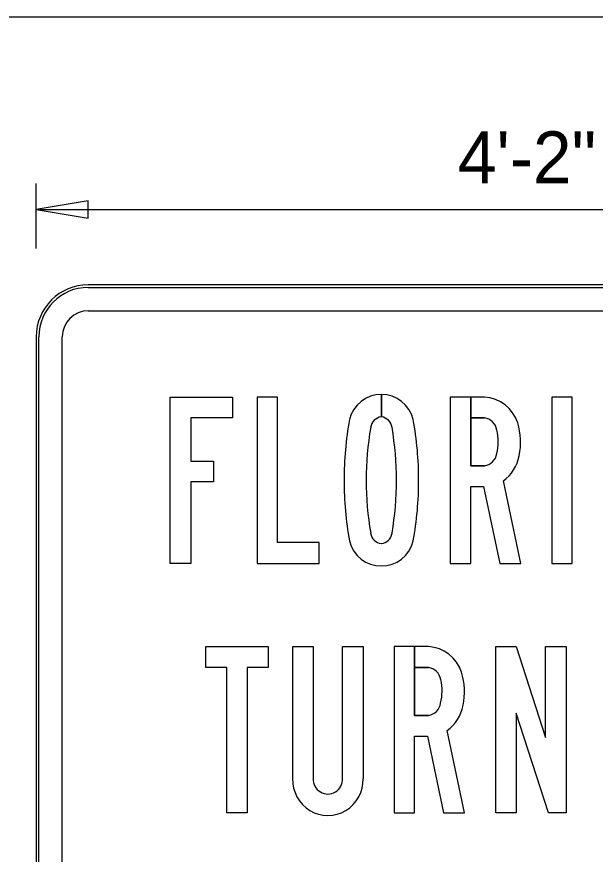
# Model space of a CAD drawing. Extents: x 17890628 to 17890844, y 17897693 to 17898031.
# Drawn here: x 17890743.43 to 17890750.86, y 17897946.37 to 17897957.11 of the extents above; entities that cross this region are included whole.
import ezdxf

# ---------------------------------------------------------------- set-up
doc = ezdxf.new("R2010")
doc.units = 0
for name, color, linetype in [('GSColorFill', 7, 'Continuous'), ('GSDims', 7, 'Continuous'), ('SheetLinesMisc2_dp', 7, 'Continuous')]:
    doc.layers.add(name, color=color, linetype=linetype)

msp = doc.modelspace()

# ---------------------------------------------------------------- linework, layer by layer
at = {"layer": 'GSColorFill'}
for p, q in [((17890756.351, 17897953.67), (17890744.351, 17897953.67)), ((17890756.351, 17897953.67), (17890744.351, 17897953.67)), ((17890756.351, 17897953.67), (17890744.351, 17897953.67)), ((17890744.351, 17897953.637), (17890756.351, 17897953.637)), ((17890744.351, 17897953.337), (17890756.351, 17897953.337)), ((17890743.684, 17897953.004), (17890743.684, 17897938.337)), ((17890743.684, 17897953.004), (17890743.684, 17897938.337)), ((17890743.684, 17897953.004), (17890743.684, 17897938.337)), ((17890743.717, 17897938.337), (17890743.717, 17897953.004)), ((17890744.017, 17897938.337), (17890744.017, 17897953.004)), ((17890748.111, 17897952.262), (17890748.111, 17897951.976)), ((17890748.111, 17897951.976), (17890748.111, 17897952.262)), ((17890748.111, 17897952.262), (17890748.111, 17897951.976)), ((17890748.111, 17897951.976), (17890748.111, 17897952.262)), ((17890747.614, 17897947.338), (17890747.614, 17897947.338)), ((17890747.614, 17897947.338), (17890747.614, 17897947.338)), ((17890747.614, 17897947.338), (17890747.614, 17897947.338))]:
    msp.add_line(p, q, dxfattribs=at)
for points in [[(17890745.957, 17897951.408), (17890745.957, 17897951.142), (17890745.665, 17897951.142), (17890745.665, 17897950.097), (17890745.403, 17897950.097), (17890745.403, 17897952.231), (17890746.201, 17897952.231), (17890746.201, 17897951.964), (17890745.665, 17897951.964), (17890745.665, 17897951.408)], [(17890745.957, 17897951.408), (17890745.957, 17897951.142), (17890745.665, 17897951.142), (17890745.665, 17897950.097), (17890745.403, 17897950.097), (17890745.403, 17897952.231), (17890746.201, 17897952.231), (17890746.201, 17897951.964), (17890745.665, 17897951.964), (17890745.665, 17897951.408)], [(17890745.957, 17897951.408), (17890745.957, 17897951.142), (17890745.665, 17897951.142), (17890745.665, 17897950.097), (17890745.403, 17897950.097), (17890745.403, 17897952.231), (17890746.201, 17897952.231), (17890746.201, 17897951.964), (17890745.665, 17897951.964), (17890745.665, 17897951.408)], [(17890746.779, 17897950.364), (17890746.779, 17897952.231), (17890746.516, 17897952.231), (17890746.516, 17897950.097), (17890747.315, 17897950.097), (17890747.315, 17897950.364)], [(17890746.779, 17897950.364), (17890746.779, 17897952.231), (17890746.516, 17897952.231), (17890746.516, 17897950.097), (17890747.315, 17897950.097), (17890747.315, 17897950.364)], [(17890746.779, 17897950.364), (17890746.779, 17897952.231), (17890746.516, 17897952.231), (17890746.516, 17897950.097), (17890747.315, 17897950.097), (17890747.315, 17897950.364)], [(17890750.561, 17897952.231), (17890750.298, 17897952.231), (17890750.298, 17897950.097), (17890750.561, 17897950.097)], [(17890750.561, 17897952.231), (17890750.298, 17897952.231), (17890750.298, 17897950.097), (17890750.561, 17897950.097)], [(17890750.561, 17897952.231), (17890750.298, 17897952.231), (17890750.298, 17897950.097), (17890750.561, 17897950.097)], [(17890746.659, 17897948.763), (17890746.391, 17897948.763), (17890746.391, 17897946.898), (17890746.128, 17897946.898), (17890746.128, 17897948.763), (17890745.86, 17897948.763), (17890745.86, 17897949.03), (17890746.659, 17897949.03)], [(17890746.659, 17897948.763), (17890746.391, 17897948.763), (17890746.391, 17897946.898), (17890746.128, 17897946.898), (17890746.128, 17897948.763), (17890745.86, 17897948.763), (17890745.86, 17897949.03), (17890746.659, 17897949.03)], [(17890746.659, 17897948.763), (17890746.391, 17897948.763), (17890746.391, 17897946.898), (17890746.128, 17897946.898), (17890746.128, 17897948.763), (17890745.86, 17897948.763), (17890745.86, 17897949.03), (17890746.659, 17897949.03)], [(17890749.841, 17897948.177), (17890749.841, 17897946.898), (17890749.578, 17897946.898), (17890749.578, 17897949.03), (17890749.841, 17897949.03), (17890750.219, 17897947.864), (17890750.219, 17897949.03), (17890750.481, 17897949.03), (17890750.481, 17897946.898), (17890750.255, 17897946.898)], [(17890749.841, 17897948.177), (17890749.841, 17897946.898), (17890749.578, 17897946.898), (17890749.578, 17897949.03), (17890749.841, 17897949.03), (17890750.219, 17897947.864), (17890750.219, 17897949.03), (17890750.481, 17897949.03), (17890750.481, 17897946.898), (17890750.255, 17897946.898)], [(17890749.841, 17897948.177), (17890749.841, 17897946.898), (17890749.578, 17897946.898), (17890749.578, 17897949.03), (17890749.841, 17897949.03), (17890750.219, 17897947.864), (17890750.219, 17897949.03), (17890750.481, 17897949.03), (17890750.481, 17897946.898), (17890750.255, 17897946.898)]]:
    msp.add_lwpolyline(points, close=True, dxfattribs=at)
for points in [[(17890749.435, 17897952.231), (17890748.996, 17897952.231), (17890748.996, 17897950.097), (17890749.258, 17897950.097), (17890749.258, 17897951.083), (17890749.423, 17897951.083), (17890749.631, 17897950.097)], [(17890749.258, 17897952.231), (17890748.996, 17897952.231), (17890748.996, 17897950.097), (17890749.258, 17897950.097), (17890749.258, 17897951.083), (17890749.423, 17897951.083), (17890749.631, 17897950.097), (17890749.899, 17897950.097), (17890749.677, 17897951.155)], [(17890749.258, 17897952.231), (17890748.996, 17897952.231), (17890748.996, 17897950.097), (17890749.258, 17897950.097), (17890749.258, 17897951.083), (17890749.423, 17897951.083), (17890749.631, 17897950.097), (17890749.899, 17897950.097), (17890749.677, 17897951.155)], [(17890749.435, 17897952.231), (17890749.258, 17897952.231), (17890749.258, 17897951.964), (17890749.435, 17897951.964)], [(17890749.435, 17897951.35), (17890749.258, 17897951.35), (17890749.258, 17897952.231)], [(17890749.435, 17897952.231), (17890749.258, 17897952.231), (17890749.258, 17897951.964), (17890749.435, 17897951.964)], [(17890749.435, 17897951.35), (17890749.258, 17897951.35), (17890749.258, 17897952.231)], [(17890749.435, 17897951.964), (17890749.258, 17897951.964), (17890749.258, 17897951.35), (17890749.435, 17897951.35)], [(17890749.631, 17897950.097), (17890749.899, 17897950.097), (17890749.677, 17897951.155)], [(17890746.974, 17897947.338), (17890746.974, 17897949.03), (17890747.236, 17897949.03), (17890747.236, 17897947.338)], [(17890746.974, 17897947.338), (17890746.974, 17897949.03), (17890747.236, 17897949.03), (17890747.236, 17897947.338)], [(17890746.974, 17897947.338), (17890746.974, 17897949.03), (17890747.236, 17897949.03), (17890747.236, 17897947.338)], [(17890747.614, 17897947.338), (17890747.614, 17897949.03), (17890747.877, 17897949.03), (17890747.877, 17897947.338)], [(17890747.614, 17897947.338), (17890747.614, 17897949.03), (17890747.877, 17897949.03), (17890747.877, 17897947.338)], [(17890747.614, 17897947.338), (17890747.614, 17897949.03), (17890747.877, 17897949.03), (17890747.877, 17897947.338)], [(17890748.715, 17897949.03), (17890748.276, 17897949.03), (17890748.276, 17897946.898), (17890748.538, 17897946.898), (17890748.538, 17897947.883), (17890748.703, 17897947.883), (17890748.91, 17897946.898)], [(17890748.538, 17897949.03), (17890748.276, 17897949.03), (17890748.276, 17897946.898), (17890748.538, 17897946.898), (17890748.538, 17897947.883), (17890748.703, 17897947.883), (17890748.91, 17897946.898), (17890749.179, 17897946.898), (17890748.957, 17897947.955)], [(17890748.538, 17897949.03), (17890748.276, 17897949.03), (17890748.276, 17897946.898), (17890748.538, 17897946.898), (17890748.538, 17897947.883), (17890748.703, 17897947.883), (17890748.91, 17897946.898), (17890749.179, 17897946.898), (17890748.957, 17897947.955)], [(17890748.715, 17897949.03), (17890748.538, 17897949.03), (17890748.538, 17897948.763), (17890748.715, 17897948.763)], [(17890748.715, 17897948.149), (17890748.538, 17897948.149), (17890748.538, 17897949.03)], [(17890748.715, 17897949.03), (17890748.538, 17897949.03), (17890748.538, 17897948.763), (17890748.715, 17897948.763)], [(17890748.715, 17897948.149), (17890748.538, 17897948.149), (17890748.538, 17897949.03)], [(17890748.715, 17897948.763), (17890748.538, 17897948.763), (17890748.538, 17897948.149), (17890748.715, 17897948.149)], [(17890748.91, 17897946.898), (17890749.179, 17897946.898), (17890748.957, 17897947.955)]]:
    msp.add_lwpolyline(points, dxfattribs=at)
for radius in [0.667, 0.667, 0.667, 0.633, 0.333]:
    msp.add_arc((17890744.351, 17897953.004), radius, 90, 180, dxfattribs=at)
for centre, major_axis, start_param, end_param in [((17890748.106, 17897951.84), (0, 0.423), 6.270788, 7.609689), ((17890748.106, 17897951.84), (0, 0.423), 6.270788, 7.609689), ((17890748.106, 17897951.84), (0, 0.423), 6.270788, 7.609689), ((17890748.116, 17897951.84), (0, 0.423), 4.956682, 6.295583), ((17890748.116, 17897951.84), (0, 0.423), 4.956682, 6.295331), ((17890748.116, 17897951.84), (0, 0.423), 4.956682, 6.295331), ((17890749.411, 17897951.751), (0, 0.48), 5.030251, 6.233097), ((17890749.411, 17897951.751), (0, 0.48), 5.030251, 6.233097), ((17890749.411, 17897951.751), (0, 0.48), 5.030251, 6.233097), ((17890748.126, 17897951.821), (0, 0.156), 0.099923, 1.436755), ((17890748.126, 17897951.821), (0, 0.156), 0.099923, 1.436755), ((17890748.126, 17897951.821), (0, 0.156), 0.099923, 1.436755), ((17890748.096, 17897951.821), (0, 0.156), 4.846431, 6.183262), ((17890748.096, 17897951.821), (0, 0.156), 4.846431, 6.182575), ((17890748.096, 17897951.821), (0, 0.156), 4.846431, 6.182575), ((17890749.403, 17897951.769), (0, 0.198), 4.908761, 6.117799), ((17890749.403, 17897951.769), (0, 0.198), 4.908761, 6.117799), ((17890749.403, 17897951.769), (0, 0.198), 4.908761, 6.117799), ((17890751.676, 17897951.183), (0, 4.105), 1.3849, 1.575497), ((17890751.676, 17897951.183), (0, 4.105), 1.3849, 1.575497), ((17890751.676, 17897951.183), (0, 4.105), 1.3849, 1.575497), ((17890744.546, 17897951.183), (0, 4.105), 4.707688, 4.898285), ((17890744.546, 17897951.183), (0, 4.105), 4.707688, 4.898285), ((17890744.546, 17897951.183), (0, 4.105), 4.707688, 4.898285), ((17890749.056, 17897951.65), (0, 0.854), 4.509585, 5.011141), ((17890749.056, 17897951.65), (0, 0.854), 4.509585, 5.011141), ((17890749.056, 17897951.65), (0, 0.854), 4.509585, 5.011141), ((17890752.088, 17897951.129), (0, 4.237), 1.401553, 1.562444), ((17890752.088, 17897951.129), (0, 4.237), 1.401553, 1.562444), ((17890752.088, 17897951.129), (0, 4.237), 1.401553, 1.562444), ((17890744.134, 17897951.129), (0, 4.237), 4.720742, 4.881632), ((17890744.134, 17897951.129), (0, 4.237), 4.720742, 4.881632), ((17890744.134, 17897951.129), (0, 4.237), 4.720742, 4.881632), ((17890748.984, 17897951.662), (0, 0.636), 4.465322, 4.943449), ((17890748.984, 17897951.662), (0, 0.636), 4.465322, 4.943449), ((17890748.984, 17897951.662), (0, 0.636), 4.465322, 4.943449), ((17890749.41, 17897951.535), (0, 0.187), 3.278526, 4.557126), ((17890749.41, 17897951.535), (0, 0.187), 3.278526, 4.557126), ((17890749.41, 17897951.535), (0, 0.187), 3.278526, 4.557126), ((17890749.374, 17897951.578), (0, 0.523), 3.768896, 4.519364), ((17890749.374, 17897951.578), (0, 0.523), 3.768896, 4.519364), ((17890749.374, 17897951.578), (0, 0.523), 3.768896, 4.519364), ((17890751.676, 17897951.145), (0, 4.105), 1.566095, 1.756692), ((17890751.676, 17897951.145), (0, 4.105), 1.566095, 1.756692), ((17890751.676, 17897951.145), (0, 4.105), 1.566095, 1.756692), ((17890752.088, 17897951.199), (0, 4.237), 1.579149, 1.740039), ((17890752.088, 17897951.199), (0, 4.237), 1.579149, 1.740039), ((17890752.088, 17897951.199), (0, 4.237), 1.579149, 1.740039), ((17890744.134, 17897951.199), (0, 4.237), 4.543146, 4.704036), ((17890744.134, 17897951.199), (0, 4.237), 4.543146, 4.704036), ((17890744.134, 17897951.199), (0, 4.237), 4.543146, 4.704036), ((17890744.546, 17897951.145), (0, 4.105), 4.526493, 4.71709), ((17890744.546, 17897951.145), (0, 4.105), 4.526493, 4.71709), ((17890744.546, 17897951.145), (0, 4.105), 4.526493, 4.71709), ((17890748.126, 17897950.506), (0, 0.156), 1.704838, 3.04167), ((17890748.126, 17897950.506), (0, 0.156), 1.704838, 3.04167), ((17890748.126, 17897950.506), (0, 0.156), 1.704838, 3.04167), ((17890748.096, 17897950.506), (0, 0.156), 3.241516, 4.578347), ((17890748.096, 17897950.506), (0, 0.156), 3.241516, 4.578347), ((17890748.096, 17897950.506), (0, 0.156), 3.241516, 4.578347), ((17890748.106, 17897950.488), (0, 0.423), 1.815089, 3.15399), ((17890748.106, 17897950.488), (0, 0.423), 1.815089, 3.15399), ((17890748.106, 17897950.488), (0, 0.423), 1.815089, 3.15399), ((17890748.116, 17897950.488), (0, 0.423), 3.129195, 4.468096), ((17890748.116, 17897950.488), (0, 0.423), 3.129195, 4.468096), ((17890748.116, 17897950.488), (0, 0.423), 3.129195, 4.468096), ((17890748.691, 17897948.551), (0, 0.48), 5.030251, 6.233097), ((17890748.691, 17897948.551), (0, 0.48), 5.030251, 6.233097), ((17890748.691, 17897948.551), (0, 0.48), 5.030251, 6.233097), ((17890748.683, 17897948.568), (0, 0.198), 4.908761, 6.117799), ((17890748.683, 17897948.568), (0, 0.198), 4.908761, 6.117799), ((17890748.683, 17897948.568), (0, 0.198), 4.908761, 6.117799), ((17890748.336, 17897948.45), (0, 0.854), 4.509585, 5.011141), ((17890748.336, 17897948.45), (0, 0.854), 4.509585, 5.011141), ((17890748.336, 17897948.45), (0, 0.854), 4.509585, 5.011141), ((17890748.264, 17897948.461), (0, 0.636), 4.465322, 4.943449), ((17890748.264, 17897948.461), (0, 0.636), 4.465322, 4.943449), ((17890748.264, 17897948.461), (0, 0.636), 4.465322, 4.943449), ((17890748.69, 17897948.334), (0, 0.187), 3.278526, 4.557126), ((17890748.69, 17897948.334), (0, 0.187), 3.278526, 4.557126), ((17890748.69, 17897948.334), (0, 0.187), 3.278526, 4.557126), ((17890748.654, 17897948.378), (0, 0.523), 3.768896, 4.519364), ((17890748.654, 17897948.378), (0, 0.523), 3.768896, 4.519364), ((17890748.654, 17897948.378), (0, 0.523), 3.768896, 4.519364), ((17890747.425, 17897947.324), (0, 0.459), 1.539768, 4.743417), ((17890747.425, 17897947.324), (0, 0.459), 1.539768, 4.743417), ((17890747.425, 17897947.324), (0, 0.459), 1.539768, 4.743417), ((17890747.425, 17897947.332), (0, 0.192), 1.536895, 4.746291), ((17890747.425, 17897947.332), (0, 0.192), 1.536895, 4.746291), ((17890747.425, 17897947.332), (0, 0.192), 1.536895, 4.746291)]:
    msp.add_ellipse(centre, major_axis=major_axis, ratio=0.985, start_param=start_param, end_param=end_param, dxfattribs=at)
at = {"layer": 'GSDims'}
for p, q in [((17890743.683, 17897954.137), (17890743.683, 17897954.971)), ((17890743.683, 17897954.637), (17890757.017, 17897954.637))]:
    msp.add_line(p, q, dxfattribs=at)
msp.add_lwpolyline([(17890743.683, 17897954.637), (17890744.35, 17897954.526), (17890744.35, 17897954.749)], close=True, dxfattribs=at)
at = {"layer": 'SheetLinesMisc2_dp'}
msp.add_line((17890726.429, 17897957.108), (17890771.912, 17897957.108), dxfattribs=at)

# ---------------------------------------------------------------- texts
at = {"layer": 'GSDims'}
msp.add_text('4\'-2"', height=0.6667, dxfattribs=at).set_placement((17890749.093, 17897954.971))

doc.saveas('drawing.dxf')
